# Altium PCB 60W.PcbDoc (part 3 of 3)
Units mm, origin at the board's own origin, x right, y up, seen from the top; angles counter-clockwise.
Board outline 118.9 x 83.5 mm, 3 copper layers (Top Layer, Mid-Layer 2, Bottom Layer); 99 components, 61 nets, 240 pads, 0 vias.
Unrouted connection lines stored in the file: 1.
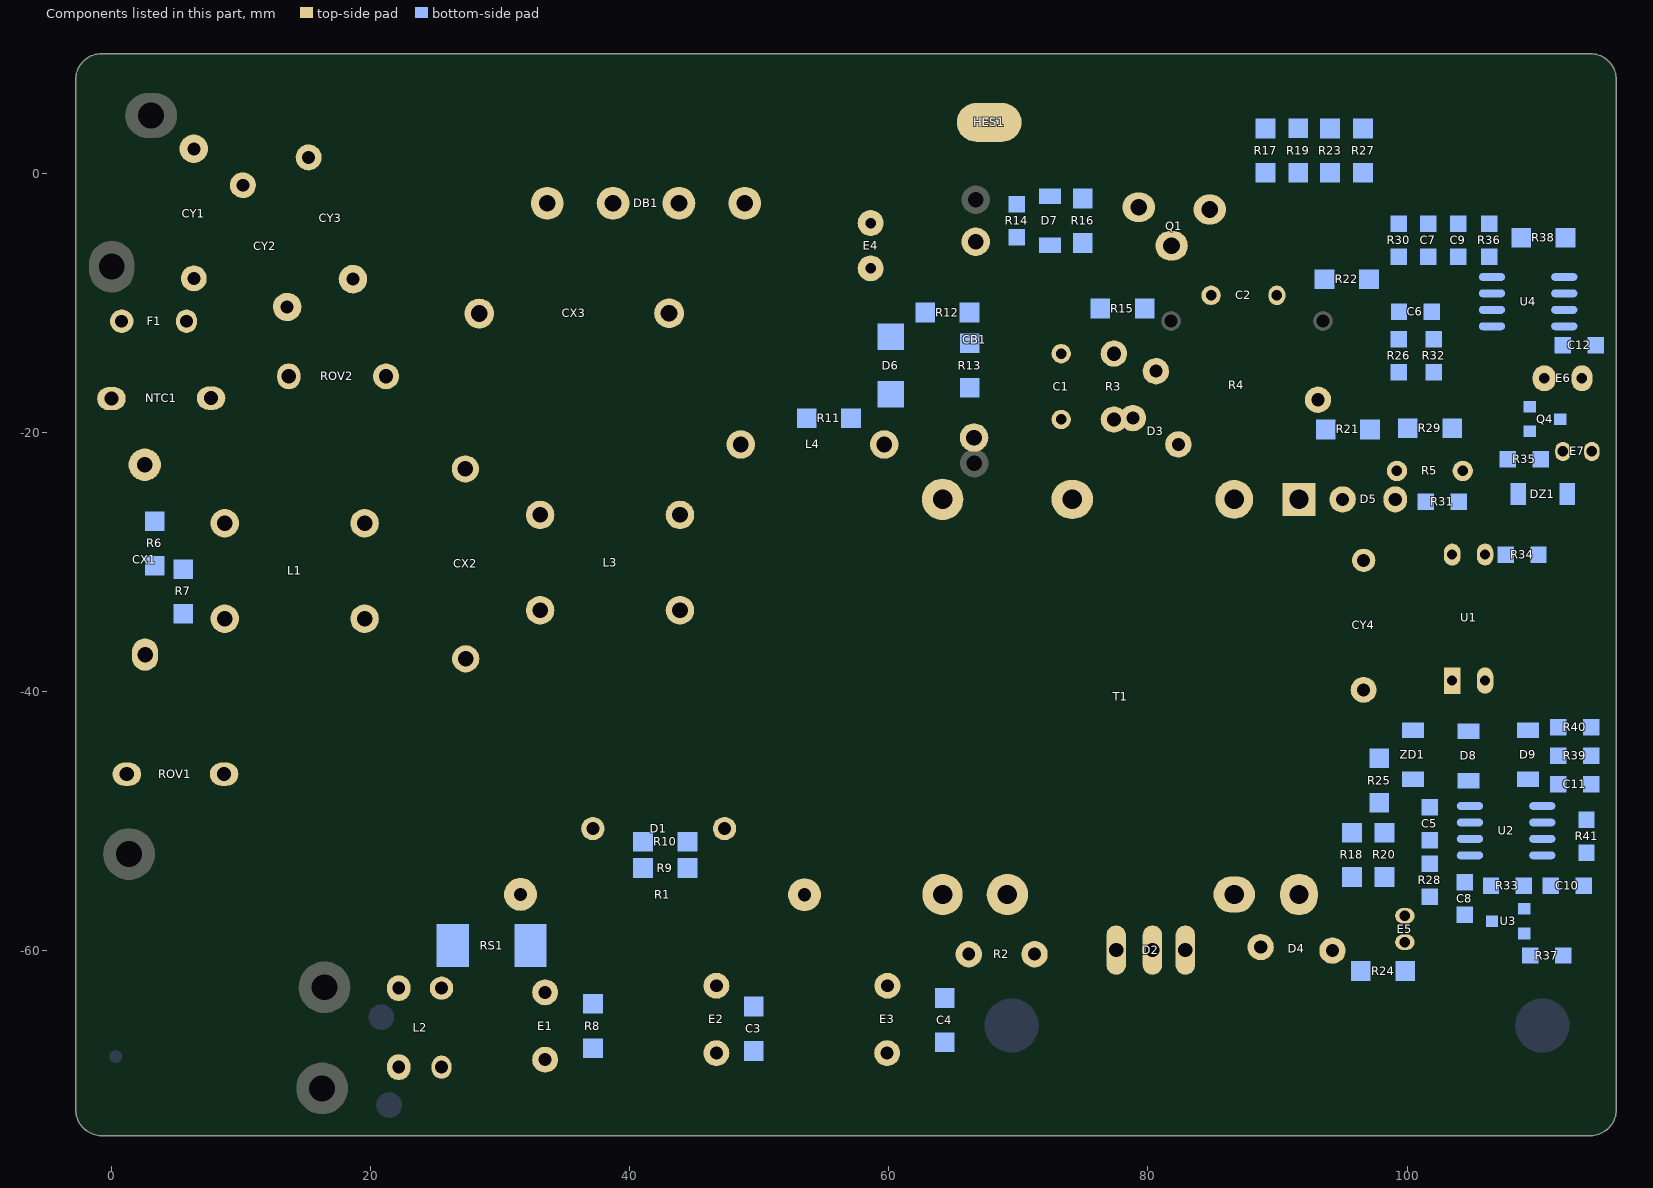
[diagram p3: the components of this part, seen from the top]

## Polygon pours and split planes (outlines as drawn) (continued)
Q3_2 on Bottom Layer "Bottom Layer-No Net" (solid): 84.89,0.84 106.02,0.84 cw(c106.02,-0.1) 106.96,-0.1 106.96,-4.25 cw(c106.7,-4.25) 106.7,-4.51 105.86,-4.51 cw(c105.86,-4.35) 105.7,-4.35 105.7,-2.32 ccw(c104.4,-2.32) 104.4,-1.02 92.09,-1.02 ccw(c92.09,-2.28) 90.83,-2.28 90.83,-10.16 cw(c90.21,-10.16) 90.21,-10.78 89.75,-10.78 cw(c89.75,-10.39) 89.36,-10.39 89.36,-5.81 ccw(c87.48,-5.81) 87.48,-3.93 84.34,-3.93 cw(c84.34,-3.04) 83.45,-3.04 83.45,-0.6 cw(c84.89,-0.6) 84.89,0.84
CY2_2 on Bottom Layer "Bottom Layer-No Net" (solid): 19.47,-6.91 17.95,-6.91 17.93,-6.91 ccw(c17.93,-7.29) 17.55,-7.29 17.55,-9.03 18.13,-9.61 18.13,-9.69 18.13,-27.61 18.14,-27.62 ccw(c18.94,-27.62) 18.94,-28.42 19.83,-28.42 26.33,-28.42 ccw(c26.33,-27.77) 26.98,-27.77 26.98,-24.6 cw(c27.24,-24.6) 27.24,-24.34 27.38,-24.34 cw(c27.38,-24.58) 27.62,-24.58 27.62,-27.64 ccw(c28.38,-27.64) 28.38,-28.4 34.23,-28.4 ccw(c34.23,-27.52) 35.11,-27.52 35.11,-22.37 ccw(c33.98,-22.37) 33.98,-21.24 23.27,-21.24 cw(c23.27,-20.32) 22.35,-20.32 22.35,-15.05 ccw(c21.57,-15.05) 21.57,-14.27 cw(c21.57,-12.63) 19.93,-12.63 19.93,-12.07 19.93,-7.37 ccw(c19.47,-7.37) 19.47,-6.91
N on Bottom Layer "Bottom Layer-No Net" (solid): 1.48,-38.01 1.48,-35.5 1.48,-34.08 cw(c2.52,-34.08) 2.52,-33.04 9.72,-33.04 13.4,-34.99 11.68,-35.66 13.41,-36.41 11.76,-37.02 13.33,-37.89 10.27,-39.37 9.9,-39.84 9.82,-39.92 9.82,-41.03 9.82,-51.71 7.09,-54.44 7,-54.53 0.31,-54.53 0.15,-54.53 cw(c0.15,-53.55) -0.83,-53.55 -0.83,-51.39 cw(c0.15,-51.39) 0.15,-50.41 4.68,-50.41 ccw(c4.68,-47.87) 7.22,-47.87 7.22,-46.71 7.22,-40.78 ccw(c5.51,-40.78) 5.51,-39.07 2.45,-39.07 cw(c2.45,-38.09) 1.47,-38.09
CX4_0 on Bottom Layer "Bottom Layer-No Net" (solid): 0.63,-16.19 -1.38,-16.19 ccw(c-1.38,-16.77) -1.96,-16.77 -1.96,-17.12 -1.96,-21.64 ccw(c-1.53,-21.64) -1.53,-22.07 0.49,-22.07 cw(c0.49,-22.4) 0.82,-22.4 0.82,-22.55 cw(c0.6,-22.55) 0.6,-22.77 -1.48,-22.77 ccw(c-1.48,-23.43) -2.14,-23.43 -2.14,-46.84 ccw(c-1.58,-46.84) -1.58,-47.4 1.85,-47.4 ccw(c1.85,-46.91) 2.34,-46.91 2.34,-45.56 ccw(c1.87,-45.56) 1.87,-45.09 1.36,-45.09 cw(c1.36,-42.89) -0.84,-42.89 -0.84,-29.79 cw(c0.98,-29.79) 0.98,-27.97 9.25,-27.97 ccw(c9.25,-27.34) 9.88,-27.34 9.88,-26.24 1.45,-17.81 1.45,-17.15 1.45,-17.01 ccw(c0.63,-17.01) 0.63,-16.19
PE on Bottom Layer "Bottom Layer-No Net" (solid): 2.13,6.48 13.99,6.48 cw(c13.99,3.94) 16.53,3.94 16.53,3.9 16.53,-0.98 cw(c15.35,-0.98) 15.35,-2.16 9.47,-2.16 cw(c9.47,-2.13) 9.44,-2.13 9.41,-2.16 7.22,-2.16 7.07,-2.16 4.26,0.65 3.08,1.83 2.52,1.83 1.31,1.83 cw(c1.31,3.11) 0.03,3.11 0.03,5.47 cw(c1.04,5.47) 1.04,6.48
F1_2 on Bottom Layer "Bottom Layer-No Net" (solid): 5.338,-8.95 5.338,-7.4 cw(c5.888,-7.4) 5.888,-6.85 7.463,-6.85 cw(c7.463,-7.183) 7.796,-7.183 7.796,-14.478 cw(c7.78,-14.478) 7.78,-14.494 8.978,-15.692 8.978,-17.755 cw(c8.426,-17.755) 8.426,-18.307 7.15,-18.307 cw(c7.15,-17.661) 6.504,-17.661 6.504,-16.354 5.001,-14.831 5.011,-10.618 5.372,-10.247 5.372,-7.367 cw(c5.889,-7.367) 5.889,-6.85
L on Bottom Layer "Bottom Layer-No Net" (solid): -1.732,-4.924 0.653,-4.924 1.021,-4.924 cw(c1.021,-5.676) 1.772,-5.676 1.772,-11.812 cw(c1.148,-11.812) 1.148,-12.436 -1.3,-12.436 cw(c-1.3,-11.763) -1.973,-11.763 -1.973,-5.165 cw(c-1.732,-5.165) -1.732,-4.924
GND on Bottom Layer "Bottom Layer-GND" (solid, remove dead copper, pour order 1005): 93.156,-28.624 97.495,-28.624 cw(c97.495,-28.985) 97.856,-28.985 97.856,-30.533 cw(c97.467,-30.533) 97.467,-30.922 86.367,-30.922 85.304,-29.859 85.304,-23.754 86.348,-22.71 86.348,-19.401 91.423,-14.326 91.423,-5.069 93.493,-2.999 95.036,-2.999 cw(c95.036,-3.379) 95.416,-3.379 95.416,-4.917 cw(c95.15,-4.917) 95.15,-5.183 93.014,-5.183 92.15,-6.047 92.15,-14.682 87.412,-19.42 87.412,-22.415 88.684,-23.687 88.684,-27.428 89.88,-28.624
GND on Bottom Layer "Bottom Layer-GND 1" (solid, remove dead copper, pour order 1006): 65.183,-2.17 65.183,-1.078 61.821,2.284 61.821,6.287 63.56,8.026 109.853,8.026 115.687,2.192 115.687,-29.164 113.33,-31.521 109.573,-31.521 109.393,-31.341 109.393,-27.806 109.824,-27.375 114.185,-27.375 114.595,-26.965 114.595,-23.071 113.467,-21.943 113.467,-17.51 112.54,-16.583 112.54,-15.024 112.856,-14.708 113.56,-14.708 113.92,-14.348 113.92,-10.052 113.539,-9.671 111.125,-9.671 110.981,-9.527 110.981,-8.988 111.139,-8.83 113.833,-8.83 114.652,-9.649 114.652,-12.509 114.832,-12.329 114.832,-9.319 114.171,-8.658 114.171,1.452 109.286,6.337 64.012,6.337 63.157,5.482 63.157,3.039 67.978,-1.782 67.978,-5.841 65.162,-5.841
GND on Bottom Layer "Bottom Layer-GND 2" (solid, remove dead copper, pour order 1007): 64.041,1.473 64.041,4.8 64.817,5.576 97.631,5.576 cw(c97.631,5.195) 98.012,5.195 98.012,3.004 cw(c97.746,3.004) 97.746,2.738 71.873,2.738 70.608,1.473 70.608,-2.996 68.611,-2.996 67.159,-4.448 66.283,-4.448 66.283,-0.812 64.041,1.43
GND on Bottom Layer "Bottom Layer-GND 3" (solid, remove dead copper, pour order 1008): 32.272,-3.186 32.272,6.474 33.228,7.43 58.983,7.43 61.023,5.39 61.023,2.393 67.971,-4.555 67.971,-5.82 67.159,-6.632 63.049,-6.632 61.259,-4.842 57.618,-4.842 57.172,-4.396 57.172,1.574 54.665,4.081 35.962,4.081 34.999,3.118 34.999,-3.111 cw(c34.496,-3.111) 34.496,-3.614 32.815,-3.614 cw(c32.815,-3.068) 32.269,-3.068
GND on Bottom Layer "Bottom Layer-GND 4" (solid, remove dead copper, pour order 1009): 104.581,-3.23 96.916,-3.23 ccw(c96.916,-3.552) 96.594,-3.552 96.594,-4.284 ccw(c96.818,-4.284) 96.818,-4.508 104.581,-4.508
U2_7 on Bottom Layer "Bottom Layer-U2_7" (solid, remove dead copper, pour order 1010): 101.122,-49.553 101.122,-48.29 101.231,-48.29 103.264,-46.257 105.591,-46.257 105.591,-47.446 103.559,-47.446 102.385,-48.62 102.385,-49.538 101.354,-49.538
U4_2 on Bottom Layer "Bottom Layer-U4_2" (solid, remove dead copper, pour order 1011): 105.218,-41.167 103.917,-42.468 103.917,-43.589 110.165,-43.589 110.165,-42.21 106.074,-38.119 105.394,-38.119 105.218,-38.295
U4_1 on Bottom Layer "Bottom Layer-U4_1" (solid, remove dead copper, pour order 1012): 103.977,-38.194 102.602,-38.194 99.613,-41.183 99.613,-43.545 101.294,-43.545 101.294,-41.975 103.05,-40.219 104.007,-40.219
DB1_3 on Bottom Layer "Bottom Layer-DB1_3" (hatched 90Degree grid 0.05 track 0.05, pour order 1013): 28.425,-11.025 27.325,-11.025 27.1,-11.25 27.1,-11.8 27.325,-12.025 27.1,-11.8 27.1,-12.075 27.275,-12.25 30.05,-12.25 38.275,-20.475 38.275,-28.725 42.525,-32.975 42.525,-39.625 42.9,-40 45.9,-40 46.375,-39.525 46.375,-34.05 40.925,-28.6 40.925,-19.35 32.95,-11.375 28.025,-11.375
CY1_2 on Bottom Layer "Bottom Layer-CY1_2" (hatched 90Degree grid 0.05 track 0.05, pour order 1015): 12.025,-9.603 12.278,-9.35 14.025,-9.35 14.55,-9.875 14.55,-16.725 15.546,-17.721 15.546,-29.425 18.671,-32.55 26.775,-32.55 27.072,-32.847 27.072,-37.2 27.522,-37.2 27.522,-32.875 27.847,-32.55 35.072,-32.55 35.622,-33.1 35.622,-39.675 35.147,-40.15 35.1,-40.197 20.122,-40.197 18.5,-38.575 16.672,-38.575 14.7,-37.9 16.672,-37.125 14.7,-36.4 16.672,-35.75 14.725,-35 16.675,-34.25 16.975,-34.25 16.975,-33.625 14.822,-31.472 14.275,-30.925 14.275,-19.363 12.912,-18 12.875,-17.963 12.875,-12.025 12.025,-11.175
CY1_2 on Bottom Layer "Bottom Layer-CY1_2 1" (hatched 90Degree grid 0.05 track 0.05, pour order 1018): 14.275,-18.65 14.275,-30.9 17.325,-33.95 17.325,-32.925 15.022,-30.622 15.022,-18.05
CY1_2 on Bottom Layer "Bottom Layer-CY1_2 2" (hatched 90Degree grid 0.05 track 0.05, pour order 1019): 29.6,-36.9 29.6,-33.025 30.05,-32.575 30.675,-32.575 30.675,-37.2 29.95,-37.925
CY1_2 on Bottom Layer "Bottom Layer-CY1_2 3" (hatched 90Degree grid 0.05 track 0.05, pour order 1020): 14.372,-18.675 14.372,-30.725 17.025,-33.378 17.025,-35.15 19.222,-35.15 19.222,-33.25 15.347,-29.375 15.347,-18.55
U1_7 on Bottom Layer "Bottom Layer-U1_7" (hatched 90Degree grid 0.05 track 0.05, pour order 1028): 73.292,2.225 108.57,2.225 108.57,1.428 77.4,1.428 75.672,-0.3 75.672,-2.475 75.525,-2.65 71.775,-2.65 71.625,-2.5 71.625,0.558
U1_7 on Bottom Layer "Bottom Layer-U1_7 1" (hatched 90Degree grid 0.05 track 0.05, pour order 1029): 108.57,2.225 109.475,2.225 110.725,0.975 110.725,-6.875 109.925,-7.675 109.925,-9.775 110.4,-10.25 112.625,-10.25 112.625,-10.775 109.825,-10.775 109.025,-9.975 109.025,-7.45 110.05,-6.425 110.05,0.35 109,1.4 108.975,1.425 108.522,1.425
U1_5 on Bottom Layer "Bottom Layer-U1_5" (hatched 90Degree grid 0.05 track 0.05, pour order 1030): 111.525,-4.275 111.525,-7.525 111.25,-7.8 113.05,-7.8 113.05,-4.225 112.475,-4.225
U1_4 on Bottom Layer "Bottom Layer-U1_4" (hatched 90Degree grid 0.05 track 0.05, pour order 1031): 103.35,-5.8 103.35,-7.1 104.475,-8.225 107.2,-8.225 107.475,-7.95 107.475,-6.075 107.225,-5.825 103.35,-5.825
U1_8 on Bottom Layer "Bottom Layer-U1_8" (hatched 90Degree grid 0.05 track 0.05, pour order 1034): 102.475,-18.075 102.475,-29.809 102.961,-30.295 103.819,-30.295 104.1,-30.014 104.1,-27.425 102.825,-26.15 102.825,-21.5 104.025,-20.3 104.025,-17.75 102.972,-17.578
U1_2 on Bottom Layer "Bottom Layer-U1_2" (hatched 90Degree grid 0.05 track 0.05, pour order 1036): 101.325,-10.05 101.325,-13.4 101.45,-13.525 102.625,-13.525 102.875,-13.275 102.875,-11.4 103.525,-10.75 106.525,-10.75 106.525,-10.25 102.975,-10.25 102.775,-10.05
C6_2 on Bottom Layer "Bottom Layer-C6_2" (hatched 90Degree grid 0.05 track 0.05, pour order 1037): 98.8,-10.05 98.8,-13.325 99.925,-13.325 99.925,-10.1
U1_3 on Bottom Layer "Bottom Layer-U1_3" (hatched 90Degree grid 0.05 track 0.05, pour order 1039): 96.35,-7.425 96.35,-6.725 97.25,-5.825 102.25,-5.825 102.25,-7.275 103.975,-9 106.55,-9 106.55,-9.525 103.45,-9.525 102.8,-8.875 96.35,-8.875
D2_1 on Bottom Layer "Bottom Layer-D2_1" (hatched 90Degree grid 0.05 track 0.05, pour order 1041): 108.425,-4.95 96.575,-4.95 95,-6.525 95,-24.875 95.725,-24.875 95.725,-6.55 96.975,-5.3 108.15,-5.3
D2_1 on Bottom Layer "Bottom Layer-D2_1 1" (hatched 90Degree grid 0.05 track 0.05, pour order 1042): 90.75,-23.975 94.15,-23.975 95.325,-22.8 96.3,-23.775 96.3,-25.9 95.875,-26.325 90.625,-26.325 90.625,-23.95
R35_2 on Bottom Layer "Bottom Layer-R35_2" (hatched 90Degree grid 0.05 track 0.05, pour order 1043): 96.5,-19.05 97.875,-19.05 98.025,-18.9 100.775,-18.9 100.775,-20.4 98.05,-20.4 97.975,-20.475 96.45,-20.475
U2_8 on Bottom Layer "Bottom Layer-U2_8" (hatched 90Degree grid 0.05 track 0.05, pour order 1044): 99.15,-59.3 99.15,-62.25 100.675,-62.25 100.675,-60.65
U2_2 on Bottom Layer "Bottom Layer-U2_2" (hatched 90Degree grid 0.05 track 0.05, pour order 1045): 111.1,-42.2 111.1,-45.475 112.3,-45.475 112.3,-42.15
U2_2 on Bottom Layer "Bottom Layer-U2_2 1" (hatched 90Degree grid 0.05 track 0.05, pour order 1046): 112.022,-43.725 113.1,-44.803 113.1,-48.675 111.475,-50.3 110.95,-50.3 110.95,-49.8 111.45,-49.8 112.725,-48.525 112.725,-45.75 112.525,-45.55 112.122,-45.55
U2_3 on Bottom Layer "Bottom Layer-U2_3" (hatched 90Degree grid 0.05 track 0.05, pour order 1047): 110.4,-51.075 111.75,-51.075 113.4,-49.425 113.4,-50.5 112.3,-51.6 110.725,-51.6
U2_3 on Bottom Layer "Bottom Layer-U2_3 1" (hatched 90Degree grid 0.05 track 0.05, pour order 1048): 112.822,-50.725 114.275,-50.725 114.475,-50.525 114.475,-49.3
U3_3 on Bottom Layer "Bottom Layer-U3_3" (hatched 90Degree grid 0.05 track 0.05, pour order 1049): 111.05,-52.35 112.575,-52.35 113.1,-51.825 113.6,-51.825 113.6,-53.025 113.5,-53.025 113.4,-52.925 110.95,-52.925
U3_3 on Bottom Layer "Bottom Layer-U3_3 1" (hatched 90Degree grid 0.05 track 0.05, pour order 1050): 112.35,-52.8 113.025,-53.475 113.025,-61.75 112.525,-62.25 103.575,-62.25 102.45,-63.375 98.975,-63.375 98.575,-62.975 98.575,-58.075 98.85,-57.8 103.075,-57.8 103.4,-58.125 106.975,-58.125 106.975,-57.25 106.375,-56.65 103.475,-56.65 103.125,-57 100.75,-57 100.525,-56.775 98.5,-56.775 97.825,-57.45 97.825,-64.325 98.275,-64.775 103.6,-64.775 105.5,-62.875 113.75,-62.875 114.275,-62.35 114.275,-53.375 114.45,-53.2 114.45,-51.825
U2_8 on Bottom Layer "Bottom Layer-U2_8 1" (hatched 90Degree grid 0.05 track 0.05, pour order 1051): 99.8,-58.75 100.7,-58.75 101.175,-59.225 101.175,-60.925 101.85,-61.6 101.55,-61.3 106.725,-61.3 107.15,-61.725 101.625,-61.725 101.15,-62.2 99.7,-62.2
U2_3 on Bottom Layer "Bottom Layer-U2_3 2" (hatched 90Degree grid 0.05 track 0.05, pour order 1052): 111.5,-60.2 111.5,-59.55 112.35,-58.7 112.6,-58.95 112.6,-60
U2_5 on Bottom Layer "Bottom Layer-U2_5" (hatched 90Degree grid 0.05 track 0.05, pour order 1053): 108.625,-56.4 108.625,-60.65 108.9,-60.925 110.1,-60.925 110.1,-56.5 109.95,-56.35 108.8,-56.35
U2_5 on Bottom Layer "Bottom Layer-U2_5 1" (hatched 90Degree grid 0.05 track 0.05, pour order 1054): 103.875,-52.575 103.875,-55.275 104.125,-55.525 106.375,-55.525 108.05,-57.2 108.972,-58.122 108.972,-56.35 108.275,-56.35 107.05,-55.125 107.05,-54.35 105.75,-53.05 105.75,-52.525
U2_6 on Bottom Layer "Bottom Layer-U2_6" (hatched 90Degree grid 0.05 track 0.05, pour order 1055): 97.175,-47.95 97.175,-49.225 97.525,-49.575 97.525,-51.525 98.925,-51.525 100,-50.45 102.625,-50.45 103,-50.825 103,-54.575 102.475,-55.1 100.975,-55.1 100.85,-55.225 100.85,-56.275 101.1,-56.525 102.5,-56.525 103.3,-55.725 103.3,-52.05 103.725,-51.625 104.725,-51.625 104.725,-51.05 103.85,-51.05 102.825,-50.025 99.375,-50.025 98.65,-49.3 98.65,-47.85
R24_2 on Bottom Layer "Bottom Layer-R24_2" (hatched 90Degree grid 0.05 track 0.05, pour order 1056): 113.625,-44.4 113.625,-47.7 114.8,-47.7 114.8,-44.4
L4_2 on Bottom Layer "Bottom Layer-L4_2" (hatched 90Degree grid 0.05 track 0.05, pour order 1057): 113.625,-43.325 114.875,-43.325 115.375,-43.825 115.25,-43.7 115.175,-43.625 115.275,-43.725 115.275,-49.05 115.1,-49.225 115,-49.325 115,-53.45 114.825,-53.625 114.825,-70.925 113.3,-72.45 115.05,-72.45 115.424,-72.076 115.775,-71.725 115.775,-42.525 115.45,-42.2 114.6,-42.2
U2_8 on Bottom Layer "Bottom Layer-U2_8 2" (hatched 90Degree grid 0.05 track 0.05, pour order 1058): 108.425,-54.325 111.675,-54.325 111.675,-55.5 108.4,-55.5
U2_8 on Bottom Layer "Bottom Layer-U2_8 3" (hatched 90Degree grid 0.05 track 0.05, pour order 1059): 109.672,-55.1 110.825,-56.253 111.572,-55.506 111.572,-54.8
C15_1 on Bottom Layer "Bottom Layer-C15_1" (hatched 90Degree grid 0.05 track 0.05, pour order 1060): 101.175,-50.85 101.175,-53.875 102.35,-53.875 102.35,-50.875
U3_3 on Bottom Layer "Bottom Layer-U3_3 2" (hatched 90Degree grid 0.05 track 0.05, pour order 1061): 90.325,-54.25 90.325,-56.575 90.975,-57.225 92.75,-57.225 93.375,-56.6 93.375,-53.475 93.925,-52.925 99.4,-52.925 99.6,-53.125 99.6,-56 98.572,-57.028 100.775,-57.028 100.175,-56.428 100.175,-52.5 99.875,-52.2 92.075,-52.2 90.325,-53.95
R22_1 on Bottom Layer "Bottom Layer-R22_1" (hatched 90Degree grid 0.05 track 0.05, pour order 1062): 95.1,-50.55 95.1,-47.175 95.9,-46.375 99.2,-46.375 99.4,-46.175 100.2,-46.175 100.2,-47.325 99.65,-47.325 99.425,-47.1 96.755,-47.1 95.95,-47.905 95.95,-49.55 96.45,-50.05 96.45,-50.525
U2_1 on Bottom Layer "Bottom Layer-U2_1" (hatched 90Degree grid 0.05 track 0.05, pour order 1063): 108.55,-46.175 110.125,-46.175 110.5,-46.55 112.275,-46.55 112.275,-48.15 111.375,-49.05 109.55,-49.05 108.575,-48.075 108.575,-46.175
U3_3 on Bottom Layer "Bottom Layer-U3_3 3" (hatched 90Degree grid 0.05 track 0.05, pour order 1064): 90.325,-54.3 90.325,-40.25 91.975,-38.6 97.45,-38.6 97.775,-38.925 97.775,-40.65 97.5,-40.925 93.6,-40.925 91.65,-42.875 91.65,-51.325 93.072,-52.747
U3_3 on Bottom Layer "Bottom Layer-U3_3 4" (hatched 90Degree grid 0.05 track 0.05, pour order 1065): 98.5,-44.45 92.05,-44.45 91.4,-43.8 91.4,-46.325 91.9,-45.825 98.5,-45.825
L4_1 on Bottom Layer "Bottom Layer-L4_1" (hatched 90Degree grid 0.05 track 0.05, pour order 1066): 95.175,-53.575 98.825,-53.575 98.825,-55.175 98.125,-55.875 95.175,-55.875
D5_2 on Bottom Layer "Bottom Layer-D5_2" (hatched 90Degree grid 0.05 track 0.05, pour order 1067): 93.15,-60.05 93.15,-60.875 94.6,-62.325 97.15,-62.325 97.15,-60.775 95.325,-58.95 93.875,-58.95 93.15,-59.675
GND on Bottom Layer "Bottom Layer-GND 5" (hatched 90Degree grid 0.05 track 0.05, pour order 1068): 113.622,-14.675 112.775,-14.675 112.5,-14.95 112.5,-16.55 113.85,-17.9 113.85,-15.95
U1_8 on Bottom Layer "Bottom Layer-U1_8 1" (hatched 90Degree grid 0.05 track 0.05, pour order 1070): 112.65,-13.6 112.65,-12.55 113.075,-12.125 113.075,-11.725 111.125,-11.825 111.125,-13.725 108.925,-15.925 104.625,-15.925 104.075,-16.475 102.925,-17.625 102.925,-20.475 104.4,-20.475 104.4,-19 105.25,-18.15 105.25,-16.75 105.55,-16.45 105.6,-16.4 108.525,-16.4 109,-16.875 109,-18.425 109.975,-18.425 111.661,-16.739 111.661,-14.625 111.687,-14.562
GND on Bottom Layer "Bottom Layer-GND 6" (hatched 90Degree grid 0.05 track 0.05, pour order 1071): 65.913,-1.212 65.188,-0.488 65.188,-0.467 65.925,-1.203 65.913,-1.214 65.913,-1.212
GND on Bottom Layer "Bottom Layer-GND 7" (hatched 90Degree grid 0.05 track 0.05, pour order 1072): 65.913,-1.212 65.188,-0.488 65.188,-0.467 65.925,-1.203 65.913,-1.214 65.913,-1.212
GND on Bottom Layer "Bottom Layer-GND 8" (hatched 90Degree grid 0.05 track 0.05, pour order 1073): 65.913,-1.212 65.188,-0.488 65.188,-0.467 65.925,-1.203 65.913,-1.214 65.913,-1.212
Q3_3 on Bottom Layer "Bottom Layer-Q3_3" (hatched 90Degree grid 0.05 track 0.05, pour order 1074): 81.675,-4.375 82.9,-4.375 cw(c82.9,-4.65) 83.175,-4.65 83.175,-6.4 85.9,-9.125 85.9,-17.525 76.55,-26.875 72.975,-26.875 72.425,-26.325 72.125,-26.025 72.125,-24.05 72.675,-23.5 77.225,-23.5 84.25,-16.475 84.25,-9.9 80.425,-6.075 80.425,-4.75 cw(c80.8,-4.75) 80.8,-4.375
Q3_1 on Bottom Layer "Bottom Layer-Q3_1" (hatched 90Degree grid 0.05 track 0.05, pour order 1075): 69.3,-4.275 77.35,-4.275 78.025,-3.6 78.025,-1.725 78.525,-1.225 80.1,-1.225 80.55,-1.675 80.55,-3.275 77.625,-6.2 69.775,-6.2 69.225,-5.65 69.225,-4.325
GND on Bottom Layer "Bottom Layer-GND 9" (hatched 90Degree grid 0.05 track 0.05, pour order 1077): 33.575,-3.6 34.7,-3.6 34.975,-3.325 34.975,3.95 34.075,3.05 33.225,2.2
DB1_3 on Bottom Layer "Bottom Layer-DB1_3 1" (hatched 90Degree grid 0.05 track 0.05, pour order 1078): 38.35,-0.9 39.6,-0.9 40.025,-1.325 40.025,-3.75 32.95,-10.825 27.35,-10.825 27,-10.475 27,-9 27.225,-8.775 32.075,-8.775 37.35,-3.5 37.35,-1.4 37.8,-0.95
DB1_2 on Bottom Layer "Bottom Layer-DB1_2" (hatched 90Degree grid 0.05 track 0.05, pour order 1079): 43.2,-0.9 44.425,-0.9 45.1,-1.575 45.1,-3.1 44.325,-3.875 44.325,-10.15 43.975,-10.5 41.9,-10.5 41.625,-10.225 41.625,-9.15 42.375,-8.4 42.375,-1.525 43,-0.9
DB1_1 on Bottom Layer "Bottom Layer-DB1_1" (hatched 90Degree grid 0.05 track 0.05, pour order 1080): 48.325,-0.975 49.975,-0.975 50.325,-1.325 50.325,-10.6 54.425,-14.7 54.425,-19.85 51.95,-22.325 48.4,-22.325 47.975,-21.9 47.975,-3.575 47.55,-3.15 47.55,-1.475 48.05,-0.975
DB1_1 on Bottom Layer "Bottom Layer-DB1_1 1" (hatched 90Degree grid 0.05 track 0.05, pour order 1081): 48,-19.025 47.275,-19.75 47.275,-21.825 47.775,-22.325 49.55,-22.325 49.55,-19.45
DB1_2 on Bottom Layer "Bottom Layer-DB1_2 1" (hatched 90Degree grid 0.05 track 0.05, pour order 1082): 41.625,-14.675 42.5,-15.55 42.5,-27.1 43.125,-27.725 45.675,-27.725 46.05,-27.35 46.05,-25.55 45.175,-24.675 45.175,-14.575 44.975,-14.375 44.3,-13.7 44.3,-11.322 44.203,-11.225 41.822,-11.225 41.625,-11.422
CY1_2 on Bottom Layer "Bottom Layer-CY1_2 4" (hatched 90Degree grid 0.05 track 0.05, pour order 1083): 35.022,-34.025 35.875,-34.025 37.775,-34.925 35.85,-35.7 37.825,-36.475 35.925,-37.125 37.825,-37.95 35.925,-38.6 34.85,-38.6 34,-37.75 34,-34.425 34.4,-34.025
DB1_3 on Bottom Layer "Bottom Layer-DB1_3 2" (hatched 90Degree grid 0.05 track 0.05, pour order 1084): 42.8,-34 41.125,-34 39.075,-34.925 41.1,-35.725 39.075,-36.475 41.075,-37.15 39.075,-37.95 41.1,-38.625 41.8,-38.625 41.8,-38.9 42.822,-39.922 42.822,-34
Dorian on Bottom Layer "Bottom Layer-Dorian" (solid, remove dead copper, pour order 1091): 72.612,-17.224 78.762,-17.224 79.854,-18.316 79.854,-19.286 78.845,-20.295 72.216,-20.295 71.708,-19.787 71.708,-18.038 72.522,-17.224
Q3_3 on Bottom Layer "Bottom Layer-Q3_3 1" (solid, remove dead copper, pour order 1092): 80.46,-22.05 82.934,-22.05 83.588,-21.396 83.588,-18.45
Lydian on Bottom Layer "Bottom Layer-Lydian" (solid, remove dead copper, pour order 1093): 88.643,-57.222 88.643,-54.639 87.952,-53.948 85.501,-53.948 84.448,-55.001 84.727,-54.722 84.727,-60.282 85.467,-61.022 85.386,-60.941 89.877,-60.941 90.191,-60.627 90.191,-58.768 88.643,-57.22
R3_2 on Bottom Layer "Bottom Layer-R3_2" (solid, remove dead copper, pour order 1094): 94.385,-7.4 92.844,-7.4 92.709,-7.535 92.709,-11.922 ccw(c92.97,-11.922) 92.97,-12.183 94.141,-12.183 ccw(c94.141,-11.889) 94.435,-11.889 94.435,-7.367
R3_2 on Bottom Layer "Bottom Layer-R3_2 1" (solid, remove dead copper, pour order 1095): 79.133,-9.683 81.421,-9.683 82.693,-10.955 82.693,-12.275 cw(c82.408,-12.275) 82.408,-12.56 81.174,-12.56 79.788,-11.174 78.99,-11.174

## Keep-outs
Keep-Out Layer:
  circle w0.254: c105.475,4.3 r1
  circle w0.254: c101.988,4.287 r1
  circle w0.254: c53.075,-5.05 r1
  circle w0.254: c53.075,-1.525 r1
  circle w0.254: c23.938,-7.363 r1
  circle w0.254: c23.938,-15.788 r1
  circle w0.254: c23.975,-11.5 r1
  circle w0.254: c20.95,-56.575 r1
  circle w0.254: c16.475,-56.575 r1
  circle w0.254: c20.825,-51.825 r1
  circle w0.254: c16.475,-51.725 r1
  circle w0.254: c58.4,-40.95 r1
  circle w0.254: c58.35,-36.925 r1
  circle w0.254: c53.75,-36.95 r1
  circle w0.254: c83.318,-33.102 r1
  circle w0.254: c74.657,-33.102 r1
  circle w0.254: c65.437,-33.254 r1
  circle w0.254: c83.318,-43.618 r1
  circle w0.254: c74.657,-43.618 r1
  circle w0.254: c65.437,-43.77 r1
  circle w0.254: c7.997,-62.135 r1
  circle w0.254: c8.073,-70.288 r1
  circle w0.254: c65.463,-38.563 r1
  circle w0.254: c74.683,-38.411 r1
  circle w0.254: c83.344,-38.411 r1
  circle w0.254: c95.125,-69.1 r1
  circle w0.254: c100.075,-69.15 r1
  circle w0.254: c104.975,-69.15 r1
  circle w0.254: c25.1,-30.525 r1
  circle w0.254: c28.6,-30.525 r1
  circle w0.254: c12.275,-51.725 r1
  circle w0.254: c12.2,-56.575 r1
  circle w0.254: c53.9,-41.05 r1
  circle w0.254: c110.05,-70.625 r1
  circle w0.254: c108.975,4.3 r1
  circle w0.254: c23.95,-19.4 r1
  circle w0.254: c87.325,-6.7 r1
  circle w0.254: c77.425,-7.8 r1
  circle w0.254: c49.375,-37.025 r1
  circle w0.254: c49.25,-41.1 r1
  circle w0.254: c24.05,-1.65 r1
  circle w0.254: c89.575,-20.65 r1
  circle w0.254: c53.15,-8.775 r1
  circle w0.254: c7.95,-65.975 r1
  circle w0.254: c3.65,-62.15 r1
  circle w0.254: c3.725,-65.975 r1
  circle w0.254: c58.525,-45.275 r1
  lines w0.127: -0.75,9.25 ccw(c-0.75,7.25) -2.75,7.25 -2.75,-72.25 ccw(c-0.75,-72.25) -0.75,-74.25 114.15,-74.25 ccw(c114.15,-72.25) 116.15,-72.25 116.15,7.25 ccw(c114.15,7.25) 114.15,9.25 ; -0.75,9.25 114.15,9.25 ; -0.75,9.25 114.15,9.25
  lines w1.2: 39.025,-16.225 41.675,-18.875 ; 41.7,-28.2 41.7,-18.903 ; 41.75,-28.275 44.671,-31.196 ; 46.3,-22.4 47.9,-24 ; 46.35,-22.425 46.35,-18.031 ; 46.35,-18.2 46.35,-12.653
  lines w1.7: 67.15,3.775 68.325,3.775

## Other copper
Bottom Layer:
  region net L4_0: 22.283,-67.799 18.015,-67.799 18.015,-72.726 22.283,-72.726
  rectangle net L4_0: 13.552,-72.378 17.66,-68.231
  region net L4_1: 85.427,-66.706 75.724,-66.706 75.724,-71.278 85.427,-71.278
  region net L4_1: 41.714,-67.164 33.611,-67.164 33.611,-70.897 41.714,-70.897
  region net L4_1: 59.468,-66.732 46.997,-66.732 46.997,-70.974 59.468,-70.974
  region net L4_1: 45.701,-66.833 41.663,-66.833 41.663,-71.304 45.701,-71.304
  region net L4_1: 32.316,-67.164 25.381,-67.164 25.381,-71.329 32.316,-71.329
  region net L4_1: 86.519,-64.076 81.428,-64.076 81.428,-68.103 86.519,-68.103
  region net L4_1: 89.948,-62.947 82.76,-62.947 82.76,-66.884 89.948,-66.884
  region net L4_2: 40.875,-48.672 30.284,-48.672 30.284,-55.429 40.875,-55.429
  region net L4_2: 31.757,-48.84 26.306,-48.84 26.306,-56.623 31.757,-56.623
  region net L4_2: 28.582,-57.131 24.873,-57.131 24.873,-64.293 28.582,-64.293
  region net L4_3: 22.587,-60.61 17.609,-60.61 17.609,-65.868 22.587,-65.868
  rectangle net L4_3: 13.418,-66.097 17.609,-60.61
  region net U3_3: 64.193,-50.873 58.563,-50.873 58.563,-56.47 64.193,-56.47
  region net U3_3: 53.982,-48.545 43.517,-48.545 43.517,-59.163 53.982,-59.163
  region net U3_3: 62.084,-50.73 55.836,-50.73 55.836,-64.395 62.084,-64.395
  region net U3_3: 61.195,-60.414 49.098,-60.414 49.098,-65.233 61.195,-65.233
  region net U3_3: 47.505,-56.678 34.978,-56.678 34.978,-59.696 47.505,-59.696
  region net U3_3: 33.484,-59.188 29.522,-59.188 29.522,-64.674 33.484,-64.674
  region net U3_3: 44.812,-60.839 32.9,-60.839 32.9,-65.233 44.812,-65.233
  region net U3_3: 45.727,-60.59 44.457,-60.59 44.457,-62.617 45.727,-62.617
  region net U3_3: 49.74,-60.407 46.692,-60.407 46.692,-62.82 49.74,-62.82
  region net U3_3: 46.159,-61.83 43.949,-61.83 43.949,-65.462 46.159,-65.462
  region net U3_3: 60.967,-62.693 46.971,-62.693 46.971,-65.513 60.967,-65.513
  region net U3_3: 34.906,-57.898 29.44,-57.898 29.44,-59.188 34.906,-59.188
  region net U3_3: 35.414,-56.75 33.332,-56.75 33.332,-58.121 35.414,-58.121
  rectangle net NewNet4: 3.275,-31.097 6.475,-29.7
  region net L4_1: 60.687,-66.681 60.824,-71.135 77.426,-71.278 76.588,-66.935 74.48,-66.706 72.219,-68.967 67.621,-68.967 65.158,-66.427 60.687,-66.681 60.662,-69.983

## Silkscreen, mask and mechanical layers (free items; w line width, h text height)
Top Overlay:
  circle w0.2: c7.626,6 r2.171
  circle w0.254: c103.063,-37.344 r0.5
  circle w0.127: c110.5,-65.775 r1.175
  circle w0.127: c69.5,-65.775 r1.175
  lines w0.127: 67,-72.775 ccw(c67.5,-72.775) 68,-72.775 68,-67.775 cw(c68.3,-67.775) 68.3,-67.475 68.5,-67.475 ccw(c68.5,-67.175) 68.8,-67.175 68.8,-66.719 cw(c69.5,-65.775) 70.2,-66.719 70.2,-67.175 ccw(c70.5,-67.175) 70.5,-67.475 71.7,-67.475 cw(c71.7,-67.775) 72,-67.775 72,-72.775 ccw(c72.5,-72.775) 73,-72.775 73,-66.075 cw(c73.3,-66.075) 73.3,-65.775 76.7,-65.775 cw(c76.7,-66.075) 77,-66.075 77,-72.775 ccw(c77.5,-72.775) 78,-72.775 78,-66.075 cw(c78.3,-66.075) 78.3,-65.775 81.7,-65.775 cw(c81.7,-66.075) 82,-66.075 82,-72.775 ccw(c82.5,-72.775) 83,-72.775 83,-66.075 cw(c83.3,-66.075) 83.3,-65.775 86.7,-65.775 cw(c86.7,-66.075) 87,-66.075 87,-72.775 ccw(c87.5,-72.775) 88,-72.775 88,-66.075 cw(c88.3,-66.075) 88.3,-65.775 91.7,-65.775 cw(c91.7,-66.075) 92,-66.075 92,-72.775 ccw(c92.5,-72.775) 93,-72.775 93,-66.075 cw(c93.3,-66.075) 93.3,-65.775 96.7,-65.775 cw(c96.7,-66.075) 97,-66.075 97,-72.775 ccw(c97.5,-72.775) 98,-72.775 98,-66.075 cw(c98.3,-66.075) 98.3,-65.775 101.7,-65.775 cw(c101.7,-66.075) 102,-66.075 102,-72.775 ccw(c102.5,-72.775) 103,-72.775 103,-66.075 cw(c103.3,-66.075) 103.3,-65.775 106.7,-65.775 cw(c106.7,-66.075) 107,-66.075 107,-72.775 ccw(c107.5,-72.775) 108,-72.775 108,-67.775 cw(c108.3,-67.775) 108.3,-67.475 109.5,-67.475 ccw(c109.5,-67.175) 109.8,-67.175 109.8,-66.719 cw(c110.5,-65.775) 111.2,-66.719 111.2,-67.175 ccw(c111.5,-67.175) 111.5,-67.475 111.7,-67.475 cw(c111.7,-67.775) 112,-67.775 112,-72.775 ccw(c112.5,-72.775) 113,-72.775 113,-63.575 ccw(c112.7,-63.575) 112.7,-63.275 67.3,-63.275 ccw(c67.3,-63.575) 67,-63.575 67,-72.775
  lines w0.2: 24.264,0.35 44.263,0.35
  lines w0.254: 6.125,6.225 9.122,6.225 ; 6.614,5.475 8.722,5.475 ; 7.107,4.675 8.072,4.675 ; 7.672,6.225 7.672,7.851 ; 15.34,-44.815 15.112,-45.577 15.874,-45.602 15.264,-46.237 ; 15.848,-46.237 15.264,-46.237 ; 50.502,-57.994 50.502,-52.146 ; 15.264,-46.237 15.112,-46.009 15.264,-46.237 ; 13.181,-44.332 17.525,-44.332 18.236,-44.332 15.163,-47.66 13.181,-44.332
  lines w0.8: 81.625,-61.95 81.625,-57.925
  lines w1: 81.79,-11.38 93.51,-11.38
  lines w1.2: 78.925,-61.925 78.925,-57.9
  lines w1.5: 66.649,-57.586 66.649,-53.036 ; 89.143,-57.241 89.143,-52.691
  text "PE" at 0.925,6.35 h0.89
  text "L" at -2.21,-5.794 h1.02
  text "+" at 55.425,-7.5 h1.1
  text "T3.15A/300V" at 9.54,-14.24 h0.89 r90
  text "N" at 0.6,-56.6 h1.02
  text "V-" at 10.53,-63.31 h1.02
  text "V+" at 10.59,-71.35 h1.02
Bottom Overlay:
  lines w0.01: 110.727,-48.103 110.727,-41.797
  lines w0.127: 105.725,-2.928 107.647,-2.928 ; 107.1,-62.6 107.7,-63.2 107.7,-63.275 ; 107.5,-3.1 107.647,-2.953 107.647,-2.928 ; 107.5,-2.78 107.647,-2.928 ; 107.7,-55.15 107.7,-63.275 ; 108.275,-62.65 107.7,-63.225 107.7,-63.275 ; 110.727,-48.103 110.727,-41.797 110.7,-41.77 110.7,-37.375 110.725,-37.35 114.95,-37.35 114.975,-37.325 ; 111,-48.103 114.425,-48.103 ; 112.6,-42.375 112.975,-42 ; 112.975,-47.35 112.975,-41.975 112.975,-42 ; 113.35,-42.35 113,-42 112.975,-42 ; 113.875,-37.35 115.15,-37.35 115.172,-37.328 115.172,-48.103
  lines w0.5: 71.1,-3.075 71.1,-0.925 ; 103.888,-49.452 105.768,-49.452 ; 103.898,-50.707 105.778,-50.707 ; 103.929,-51.972 105.809,-51.972 ; 105.569,-9.879 107.449,-9.879 ; 105.569,-8.602 107.449,-8.602 ; 105.58,-11.156 107.46,-11.156 ; 109.503,-49.441 111.383,-49.441 ; 109.513,-51.993 111.393,-51.993 ; 109.513,-50.717 111.393,-50.717 ; 111.244,-8.588 113.124,-8.588 ; 111.27,-9.874 113.15,-9.874 ; 111.29,-11.16 113.17,-11.16
  lines w0.8: 81.6,-61.925 81.6,-57.9
  lines w1.2: 78.925,-61.925 78.925,-57.9 ; 79.256,-5.369 81.901,-2.724 84.379,-5.202
  lines w1.5: 66.669,-57.586 66.669,-53.036 ; 89.143,-57.241 89.143,-52.691
Bottom Solder:
  rectangle: 95.04,-38.51 98.15,-30.97
  region: 16.56,-33.744 11.372,-33.744 11.372,-38.9 16.56,-38.9
  region: 38.244,-34.346 34.739,-34.346 34.739,-39.502 38.244,-39.502
  region: 42.334,-34.346 38.651,-34.346 38.651,-39.502 42.334,-39.502
  region: 37.355,-34.6 34.739,-34.6 34.739,-39.502 37.355,-39.502
  lines w0.5: 86.504,-59.737 87.659,-59.737 ; 87.542,-60.122 87.542,-59.302 ; 87.927,-60.289 87.927,-59.235 ; 88.546,-60.523 85.717,-59.804 88.697,-58.716 89.132,-58.716 89.484,-59.068 89.484,-59.569
  lines w0.6: -1.34,-45.76 -1.34,-27.33
  lines w1: 18.85,-17.063 18.85,-14.65 ; 18.85,-12.875 18.85,-10.462
  lines w1.2: 13.775,-13.425 13.775,-12.725 ; 13.888,-17.513 14.65,-18.275 ; 14.925,-24.05 14.925,-20.265 ; 14.95,-28.4 14.95,-26.063 ; 15.155,-30.08 17.5,-32.425 ; 31.45,-24.525 31.45,-22.275 ; 32.65,-39.275 32.65,-36.425
  lines w1.5: 3.4,-23.7 5.875,-23.7 ; 4.05,-36.65 7.675,-36.65 ; 6.075,-53.125 8.45,-50.75 ; 8.65,-44 8.65,-40.05 ; 19.376,-36.95 25.25,-36.95 ; 19.603,-22.8 25.075,-22.775 ; 19.7,-24.75 24.929,-24.75 ; 21.19,-38.95 25.425,-38.95 ; 25.89,-55.769 28.887,-55.769 ; 25.915,-53.194 28.912,-53.194 ; 26.22,-50.425 28.683,-50.425 ; 27.007,-67.9 30.258,-67.9 ; 27.058,-70.72 31.274,-70.72 ; 29.675,-27.39 29.675,-23.275 ; 30.15,-38.4 30.15,-35.428 ; 30.6,-9.65 32.175,-9.65 ; 30.665,-52.762 37.65,-52.762 ; 31.198,-50.4 34.83,-50.4 ; 32.325,-12.85 32.35,-12.85 38.8,-19.3 ; 33.675,0.125 33.675,4.3 35.275,5.9 35.575,5.9 57.35,5.9 59.175,4.075 59.175,2.525 ; 34,-8.3 37.225,-5.075 ; 34.195,-54.667 38.793,-54.667 ; 34.856,-70.44 45.27,-70.44 ; 35.033,-57.791 42.501,-57.791 ; 35.364,-61.423 44.177,-61.423 ; 39.377,-63.684 44.762,-63.684 ; 39.575,-27.425 39.575,-21.075 ; 39.605,-67.976 44.609,-67.976 ; 40.575,-29.625 40.575,-29.65 42.2,-31.275 ; 43.175,-14.774 43.175,-12.9 ; 43.375,-8.25 43.375,-4.8 ; 43.85,-22.6 43.85,-17.175 ; 45.072,-37.925 45.072,-35.6 ; 45.625,-57.639 50.807,-57.639 ; 46.565,-52.863 53.296,-52.863 ; 47.276,-54.895 50.934,-54.895 ; 48.292,-70.389 58.681,-70.389 ; 49.125,-8.375 49.125,-5.625 ; 49.207,-50.603 53.296,-50.603 ; 49.325,-17.025 49.325,-11.725 ; 49.715,-61.753 54.261,-61.753 ; 51.5,-15.65 51.5,-13.75 ; 51.797,-68.18 57.512,-68.18 ; 54.109,-64.497 60.891,-64.497 ; 57.5,-60.458 61.322,-60.458 ; 57.5,-58.121 61.526,-58.121 ; 57.5,-55.784 61.348,-55.784 ; 57.5,-53.651 61.018,-53.651 ; 57.5,-51.517 66.91,-51.517 ; 59.175,-0.9 59.175,3.05 ; 61.678,-70.339 87.561,-70.339 ; 65.15,0.85 69.4,0.85 ; 71.432,-56.775 76.969,-56.775 ; 71.94,-54.591 82.658,-54.591 ; 75.191,-68.027 90.532,-68.103 ; 77.125,-25.075 77.25,-25.075 79.225,-23.1 ; 78.442,-65.995 91.117,-65.995 ; 80.22,-63.785 91.218,-63.785 ; 83.1,-19.25 85.075,-17.275 85.075,-12.725
  lines w2: 22.674,-34.325 25.925,-34.325 ; 22.809,-27.025 25.4,-27.025 ; 61.779,-19.183 64.472,-19.183 ; 67.469,-17.253 70.314,-14.408 70.314,-14.332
